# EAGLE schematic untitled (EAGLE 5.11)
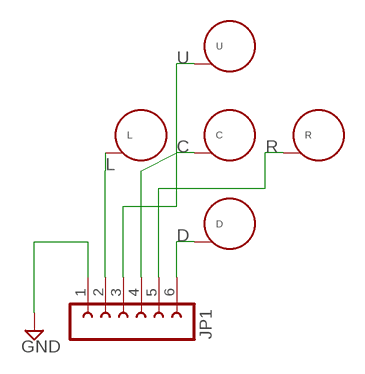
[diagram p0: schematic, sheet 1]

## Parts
C  TOUCH-PAD-10MM  [TOUCH-PAD-10MM]
D  TOUCH-PAD-10MM  [TOUCH-PAD-10MM]
JP1  FE06-1  [FE06]
L  TOUCH-PAD-10MM  [TOUCH-PAD-10MM]
R  TOUCH-PAD-10MM  [TOUCH-PAD-10MM]
U  TOUCH-PAD-10MM  [TOUCH-PAD-10MM]

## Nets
C: C.1 JP1.4
D: D.1 JP1.6
GND: JP1.1
L: JP1.2 L.1
R: JP1.5 R.1
U: JP1.3 U.1

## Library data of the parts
C D L R U = trl:TOUCH-PAD-10MM
JP1 = con-lsta:FE06-1: FEMALE HEADER; OC_FARNELL: unknown; OC_NEWARK: unknown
